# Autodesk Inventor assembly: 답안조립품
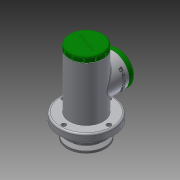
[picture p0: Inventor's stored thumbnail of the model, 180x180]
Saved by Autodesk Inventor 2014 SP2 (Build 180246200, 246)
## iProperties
Created: 2016-08
Part Number: 답안조립품
Document SubType Name: Assembly
Designer: 이도윤
Author: 이도윤
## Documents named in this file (25)
- C:\Users\201-13\Desktop\460807V1014\답안조립품.iam
- C:\Users\201-13\Desktop\460807V1014\본체.ipt
- C:\Users\201-13\Desktop\460807V1014\V-벨트풀리.ipt
- C:\Users\201-13\Desktop\460807V1014\너트 M10.ipt
- C:\Users\201-13\Desktop\460807V1014\링크.ipt
- C:\Users\201-13\Desktop\460807V1014\멈춤링 15 x 1.ipt
- C:\Users\201-13\Desktop\460807V1014\멈춤링 35x1.6.ipt
- C:\Users\201-13\Desktop\460807V1014\베어링 15 x 35 x 11.ipt
- C:\Users\201-13\Desktop\460807V1014\볼트 M4 x 10.ipt
- C:\Users\201-13\Desktop\460807V1014\볼트 M4 x 12.ipt
- C:\Users\201-13\Desktop\460807V1014\부시1.ipt
- C:\Users\201-13\Desktop\460807V1014\부시2.ipt
- C:\Users\201-13\Desktop\460807V1014\분할핀 1.6 x 12.ipt
- C:\Users\201-13\Desktop\460807V1014\사이드 커버.ipt
- 사이드 커버.ipt
- C:\Users\201-13\Desktop\460807V1014\슬라이더.ipt
- C:\Users\201-13\Desktop\460807V1014\오일 실 15 25 7.ipt
- C:\Users\201-13\Desktop\460807V1014\와셔 4x16.ipt
- C:\Users\201-13\Desktop\460807V1014\와셔 10x21.ipt
- C:\Users\201-13\Desktop\460807V1014\클래스터 핀 6 x 24.ipt
- C:\Users\201-13\Desktop\460807V1014\키 4 x 4 x 18.ipt
- C:\Users\201-13\Desktop\460807V1014\탑 부시.ipt
- C:\Users\201-13\Desktop\460807V1014\탑 커버.ipt
- 탑 커버.ipt
- C:\Users\201-13\Desktop\460807V1014\편심축.ipt
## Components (6 placed, 3 different names)
1. V-벨트풀리:1
2. ISO 4017 M4 x 10:1
3. ISO 4762 M4 x 12:1
4. ISO 4762 M4 x 12:2
5. ISO 4762 M4 x 12:3
6. ISO 4762 M4 x 12:4
